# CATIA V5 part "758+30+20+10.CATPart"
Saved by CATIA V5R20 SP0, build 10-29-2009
Part number: 758+30+20+10
Revision: TUTTO
Definition: NON CONOSCIUTO
Nomenclature: 758+30+20+10
Source: Unknown
Bounding box of the stored display mesh (mm): x -15 to 15, y 0 to 20, z -15 to 15
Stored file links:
  C:\Users\Utente\Desktop\IO LAVORO\3D X SITO CF\X 3D SITO CF 27-09-2020\758\758+30+20+10.CATPart
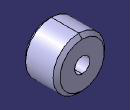
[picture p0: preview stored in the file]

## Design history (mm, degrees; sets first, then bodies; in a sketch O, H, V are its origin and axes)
Body1 "Importato1" (main body)
  Solid1: solid without history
